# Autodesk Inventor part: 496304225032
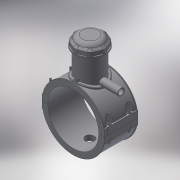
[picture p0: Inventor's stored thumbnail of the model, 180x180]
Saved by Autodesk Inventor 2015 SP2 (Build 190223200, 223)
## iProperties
Created: 2017-07
Part Number: 496304225032
Material: Generic
Description: PLASSON TAPPING SADDLE 225x32
Document SubType Name: Modeling
Designer: KIM
Mass: 1599.91 g
Surface Area: 3436.17 cm^2
Volume: 1599.91 cm^3
Density: 1 g/cm^3
Appearance: Default
Author: KIM
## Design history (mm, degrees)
derived "496304.ipt"
feature "Solid1::496304.ipt"
feature "Solid2::496304.ipt"
feature "Solid4::496304.ipt"
feature "Solid5::496304.ipt"
tag "TaggingFeature1" dims "B_" = 227
body "Solid1"
body "Solid2"
other parameters: "d_" = 225, "L_" = 176, "d_t" = 6, "H_2" = 177, "H_1" = 56, "d_1" = 32, "H_" = 132, "d1" = 256.5, "d148" = 3.375, "d160" = 3.375, "d169" = 3.375, "d192" = 6.3, "d0" = 225, "d2" = 295.1, "d3" = 56.25, "d4" = 176, "d5" = 0, "d6" = 0.1, "d8" = 0, "d19" = 6, "d20" = 6, "d21" = 105.6, "d23" = 0, "d24" = 52.8, "d26" = 0, "d29" = 3, "d30" = 75, "d31" = 6, "d32" = 0, "d33" = 0, "d34" = 0.6, "d40" = 133.38, "d43" = 0, "d45" = 0, "d47" = 233.85, "d70" = 15, "d72" = 0, "d73" = 6, "d75" = 5, "d76" = 0, "d77" = 11.25, "d78" = 142.5, "d79" = 15, "d80" = 70.4, "d82" = 5 deg, "d84" = 4, "d85" = 14, "d86" = 0, "d87" = 3, "d88" = 0, "d89" = 1, "d90" = 1, "d91" = 140.8, "d92" = 0, "d93" = 0.5, "d94" = 118.42105, "d96" = 261.63, "d97" = 3.52, "d98" = 0, "d102" = 2.25, "d120" = 140 deg, "d121" = 24.228, "d122" = 20 deg, "d123" = 513, "d124" = 153.9, "d126" = 0, "d143" = 231.75, "d145" = 24.23077, "d149" = 3.375, "d150" = 26.65385, "d153" = 176, "d154" = 0, "d156" = 128.25, "d157" = 160 deg, "d159" = 6.3, "d161" = 3.375, "d162" = 105.6, "d163" = 0, "d164" = 112.5, "d167" = 22.5, "d168" = 125.12195, "d170" = 3.375, "d172" = 0, "d173" = 1, "d175" = 112.5, "d176" = 20 deg, "d177" = 15.75, "d178" = 31.5, "d180" = 0, "d183" = 12.6, "d184" = 12.6, "d185" = 57.2, "d186" = 57.2, "d187" = 128.25, "d188" = 9.45, "d189" = 15.75, "d190" = 0, "d191" = 192.375, "d193" = 6.3, "d194" = 6.16, "d195" = 90 deg, "d197" = 0, "d199" = 0, "d200" = 15.75, "d202" = 0, "d203" = 177, "d204" = 85.5, "d205" = 63, "d206" = 76.5, "d207" = 132.75, "d208" = 138.06, "d209" = 164.61, "d210" = 77.4, "d212" = 72, "d213" = 36, "d216" = 0, "d217" = 22.5, "d218" = 22.5, "d219" = 4.5, "d222" = 225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
